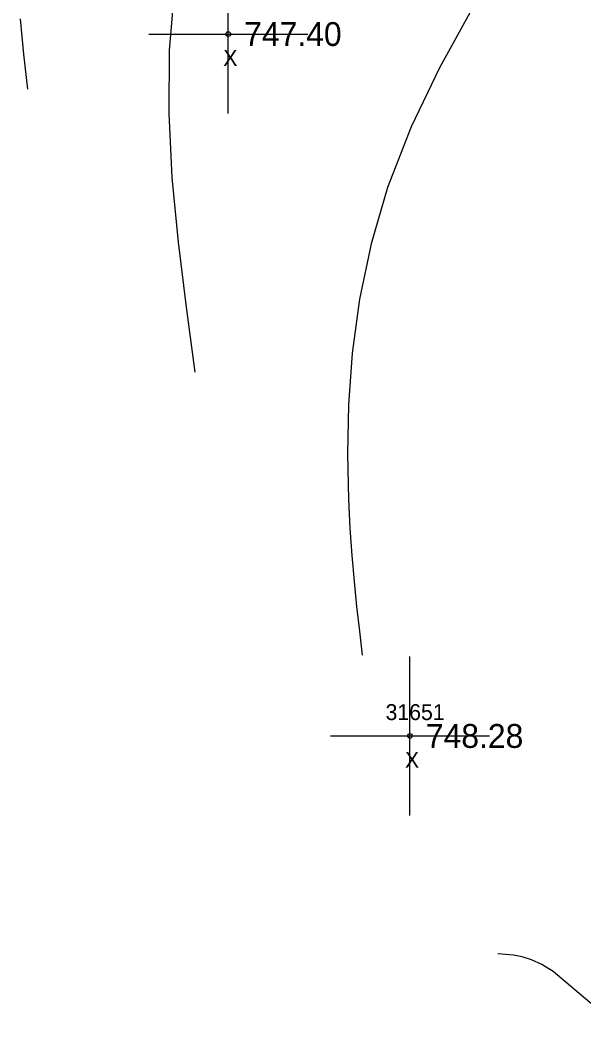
# Model space of a CAD drawing. Extents: x 1376587 to 1378239, y 1000335 to 1003031.
# Drawn here: x 1377806.5 to 1377841.9, y 1000654.4 to 1000717.4 of the extents above; entities that cross this region are included whole.
import ezdxf

# ---------------------------------------------------------------- set-up
doc = ezdxf.new("R2010")
doc.units = 0
for name, color, linetype in [('RD_DTM_Minor1', 7, 'Continuous'), ('RD_EX_Misc', 7, 'Continuous'), ('RD_EX_Misc_txCode', 7, 'Continuous'), ('RD_EX_TX_Misc_ELEV', 7, 'Continuous'), ('RD_SMD_Locator', 7, 'Continuous')]:
    doc.layers.add(name, color=color, linetype=linetype)

msp = doc.modelspace()

# ---------------------------------------------------------------- linework, layer by layer
at = {"layer": 'RD_DTM_Minor1'}
for points in [[(1377816.167, 1000719.469), (1377815.842, 1000715.53), (1377815.812, 1000711.539), (1377816.018, 1000707.507), (1377816.4, 1000703.443), (1377816.901, 1000699.359), (1377817.46, 1000695.264)], [(1377834.769, 1000717.883), (1377832.846, 1000714.412), (1377831.072, 1000710.703), (1377829.582, 1000706.886), (1377828.544, 1000703.343), (1377827.821, 1000699.857), (1377827.365, 1000696.467), (1377827.129, 1000693.211), (1377827.064, 1000690.131), (1377827.125, 1000687.263), (1377827.215, 1000685.449), (1377827.334, 1000683.732), (1377827.478, 1000682.093), (1377827.639, 1000680.513), (1377827.812, 1000678.972), (1377827.991, 1000677.451)], [(1377806.457, 1000717.499), (1377806.674, 1000715.278), (1377806.928, 1000713.077)], [(1377843.67, 1000654.438), (1377840.001, 1000657.558), (1377839.281, 1000657.984), (1377838.636, 1000658.278), (1377838.053, 1000658.465), (1377837.514, 1000658.574), (1377837.006, 1000658.63), (1377836.514, 1000658.659)]]:
    msp.add_lwpolyline(points, dxfattribs=at)
at = {"layer": 'RD_EX_Misc'}
for p, q in [((1377819.56, 1000711.544), (1377819.56, 1000721.544)), ((1377814.56, 1000716.544), (1377824.56, 1000716.544)), ((1377830.993, 1000667.374), (1377830.993, 1000677.374)), ((1377825.993, 1000672.374), (1377835.993, 1000672.374))]:
    msp.add_line(p, q, dxfattribs=at)
at = {"layer": 'RD_SMD_Locator'}
for centre in [(1377819.56, 1000716.544), (1377830.993, 1000672.374)]:
    msp.add_circle(centre, 0.15, dxfattribs=at)

# ---------------------------------------------------------------- texts
at = {"layer": 'RD_EX_Misc_txCode'}
for s, p in [('X', (1377819.245, 1000714.544)), ('31651', (1377829.458, 1000673.374)), ('X', (1377830.678, 1000670.374))]:
    msp.add_text(s, height=1, dxfattribs=at).set_placement(p)
at = {"layer": 'RD_EX_TX_Misc_ELEV'}
for s, p in [('747.40', (1377820.56, 1000715.794)), ('748.28', (1377831.993, 1000671.624))]:
    msp.add_text(s, height=1.5, dxfattribs=at).set_placement(p)

doc.saveas('drawing.dxf')
